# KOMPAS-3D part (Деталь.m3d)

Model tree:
1. Эскиз:1
2. Операция выдавливания:1
     Расстояние 1 = 25
3. Эскиз:2
4. Вырезать элемент выдавливания:1
     Расстояние 1 = 10
5. Эскиз:3
6. Вырезать элемент выдавливания:2
     Расстояние 1 = 30
7. Эскиз:4
8. Эскиз:5
9. Операция выдавливания:2
     Расстояние 1 = 40
10. Эскиз:6
11. Операция выдавливания:3
     Расстояние 1 = 65
12. Эскиз:7
13. Операция выдавливания:4
     Расстояние 1 = 65; Расстояние 2 = 15
14. Эскиз:8
15. Операция выдавливания:5
     Расстояние 1 = 65; Расстояние 2 = 15
16. Эскиз:9
17. Вырезать элемент выдавливания:3
     Расстояние 1 = 15
18. Эскиз:10
19. Вырезать элемент выдавливания:4
     Расстояние 1 = 15
20. Вырезать элемент выдавливания:5
     Расстояние 1 = 15
21. Эскиз:11
22. Эскиз:12
23. Вырезать элемент выдавливания:6
     Расстояние 1 = 15
24. Эскиз:13
25. Вырезать элемент выдавливания:7
     Расстояние 1 = 40
26. Эскиз:14
27. Вырезать элемент выдавливания:8
     Расстояние 1 = 30
28. Эскиз:15
29. Вырезать элемент выдавливания:9
     Расстояние 1 = 20
